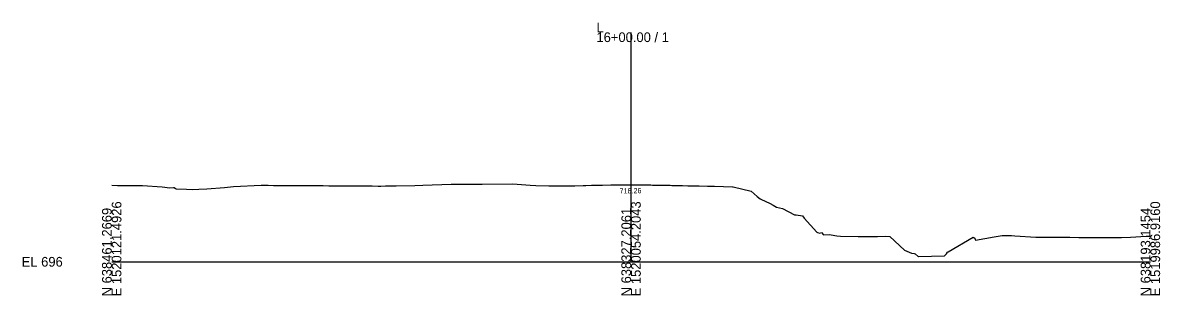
# Model space of a CAD drawing. Extents: x -26 to 3903, y -10 to 9531.
# Drawn here: x -25.7 to 302.8, y 5990.3 to 6069.2 of the extents above; entities that cross this region are included whole.
import ezdxf

# ---------------------------------------------------------------- set-up
doc = ezdxf.new("R2010")
doc.units = 0
for name, color, linetype in [('Default', 7, 'Continuous'), ('Exist Cross Section Cell', 7, 'Continuous'), ('Exist XS Center Line Elevation Label', 7, 'Continuous'), ('Exist XS Ground Line', 7, 'Continuous')]:
    doc.layers.add(name, color=color, linetype=linetype)

msp = doc.modelspace()

# ---------------------------------------------------------------- linework, layer by layer
at = {"layer": 'Exist Cross Section Cell'}
for p, q in [((150, 6000), (150, 6066.37)), ((0, 6000), (150, 6000)), ((150, 6000), (300, 6000))]:
    msp.add_line(p, q, dxfattribs=at)
at = {"layer": 'Exist XS Ground Line'}
msp.add_lwpolyline([(0, 6022.12), (1.65, 6022.11), (8.85, 6022.05), (14.58, 6021.71), (16.81, 6021.41), (17.85, 6021.45), (18.01, 6021.46), (18.41, 6021.21), (18.6, 6021.13), (21.62, 6021.01), (23.44, 6020.93), (25.21, 6020.97), (27.51, 6021.12), (32.62, 6021.48), (35.16, 6021.77), (43.15, 6022.14), (43.26, 6022.14), (43.29, 6022.14), (43.4, 6022.14), (43.41, 6022.14), (43.82, 6022.13), (44.45, 6022.13), (45.18, 6022.13), (46.71, 6022.11), (47.02, 6022.1), (47.81, 6022.1), (49.37, 6022.08), (49.7, 6022.08), (49.83, 6022.08), (50.29, 6022.08), (52.63, 6022.07), (54.94, 6022.07), (55.27, 6022.07), (55.43, 6022.07), (55.92, 6022.07), (58.23, 6022.04), (58.99, 6022.04), (60.51, 6022.03), (61.03, 6022.03), (62.72, 6022.01), (63.82, 6022.01), (64.58, 6022), (66.08, 6021.99), (66.61, 6021.98), (68.29, 6021.97), (69.4, 6021.97), (70.16, 6021.96), (71.67, 6021.95), (72.02, 6021.94), (72.19, 6021.94), (75.04, 6021.94), (75.08, 6021.94), (75.1, 6021.94), (75.2, 6021.94), (77, 6021.92), (77.7, 6021.92), (79.1, 6021.95), (80.7, 6021.98), (82.16, 6022.01), (87.52, 6022.06), (89.87, 6022.14), (98, 6022.48), (98.39, 6022.49), (98.52, 6022.5), (106.98, 6022.47), (115.88, 6022.55), (115.9, 6022.54), (120.88, 6022.18), (122.45, 6022.1), (126.21, 6022.02), (130.99, 6021.94), (131.18, 6021.94), (131.54, 6021.95), (131.79, 6021.95), (133.09, 6021.99), (133.37, 6022), (133.76, 6022.01), (136.17, 6022.09), (136.97, 6022.11), (138.55, 6022.15), (138.96, 6022.16), (139.36, 6022.16), (141.74, 6022.19), (144.11, 6022.24), (144.53, 6022.25), (144.95, 6022.25), (147.32, 6022.27), (148.95, 6022.27), (149.64, 6022.28), (150, 6022.27), (150.14, 6022.26), (151.91, 6022.26), (152.96, 6022.25), (153.73, 6022.25), (155.28, 6022.23), (155.75, 6022.22), (156.22, 6022.21), (158.53, 6022.17), (159.59, 6022.16), (160.82, 6022.13), (161.15, 6022.13), (161.32, 6022.12), (161.82, 6022.11), (164.11, 6022.07), (164.88, 6022.05), (166.4, 6022.02), (166.74, 6022.01), (166.9, 6022.01), (167.4, 6021.99), (169.71, 6021.93), (172.03, 6021.87), (172.38, 6021.86), (172.53, 6021.88), (172.73, 6021.87), (173.69, 6021.84), (174.14, 6021.84), (179.29, 6021.67), (179.34, 6021.67), (179.38, 6021.66), (179.46, 6021.64), (184.71, 6020.44), (186.43, 6018.85), (187.26, 6018.26), (187.5, 6018.15), (190.14, 6016.9), (191.01, 6016.42), (191.99, 6015.85), (193.72, 6015.4), (197.19, 6013.62), (197.67, 6013.63), (199.54, 6013.26), (200.01, 6012.58), (203.67, 6008.58), (203.83, 6008.48), (204.49, 6008.32), (204.97, 6008.49), (205.58, 6007.82), (207.31, 6007.86), (207.83, 6007.84), (209.41, 6007.48), (210.53, 6007.38), (215.61, 6007.34), (221.09, 6007.29), (221.21, 6007.31), (223.6, 6007.41), (224.72, 6007.32), (228.93, 6003.37), (230.97, 6002.46), (231.8, 6002.43), (232.01, 6002.28), (232.95, 6001.56), (233.04, 6001.5), (240.5, 6001.77), (240.51, 6001.77), (240.53, 6001.77), (240.53, 6001.77), (241.14, 6002.28), (241.44, 6002.78), (241.44, 6002.78), (241.55, 6002.87), (248.82, 6007.15), (249.31, 6006.87), (249.46, 6006.29), (254.89, 6007.23), (257.14, 6007.62), (259.91, 6007.56), (260.83, 6007.51), (266.88, 6007.16), (271.65, 6007.09), (276.68, 6007.14), (279.28, 6007.03), (291.66, 6007.07), (294.22, 6007.1), (298.73, 6007.37), (299.96, 6007.45), (300, 6007.45)], dxfattribs=at)

# ---------------------------------------------------------------- texts
at = {"layer": 'Default'}
msp.add_text('-', height=0.0001, dxfattribs=at).set_placement((0, 6000))
at = {"layer": 'Exist Cross Section Cell'}
for s, p in [('L', (140, 6066.37)), ('16+00.00 / 1', (140, 6063.57)), ('EL 696', (-26, 5998.6))]:
    msp.add_text(s, height=2.8, dxfattribs=at).set_placement(p)
for s, p in [('E 1520121.4926', (2.8, 5990)), ('E 1520054.2043', (152.8, 5990)), ('N 638193.1454', (300, 5990)), ('E 1519986.9160', (302.8, 5990)), ('N 638461.2669', (0, 5990)), ('N 638327.2061', (150, 5990))]:
    msp.add_text(s, height=2.8, rotation=90, dxfattribs=at).set_placement(p)
at = {"layer": 'Exist XS Center Line Elevation Label'}
msp.add_text('718.26', height=1.5, rotation=0.8401, dxfattribs=at).set_placement((146.68, 6019.75))

doc.saveas('drawing.dxf')
